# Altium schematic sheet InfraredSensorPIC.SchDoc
size A; SheetNumber: 1; SheetTotal: 1
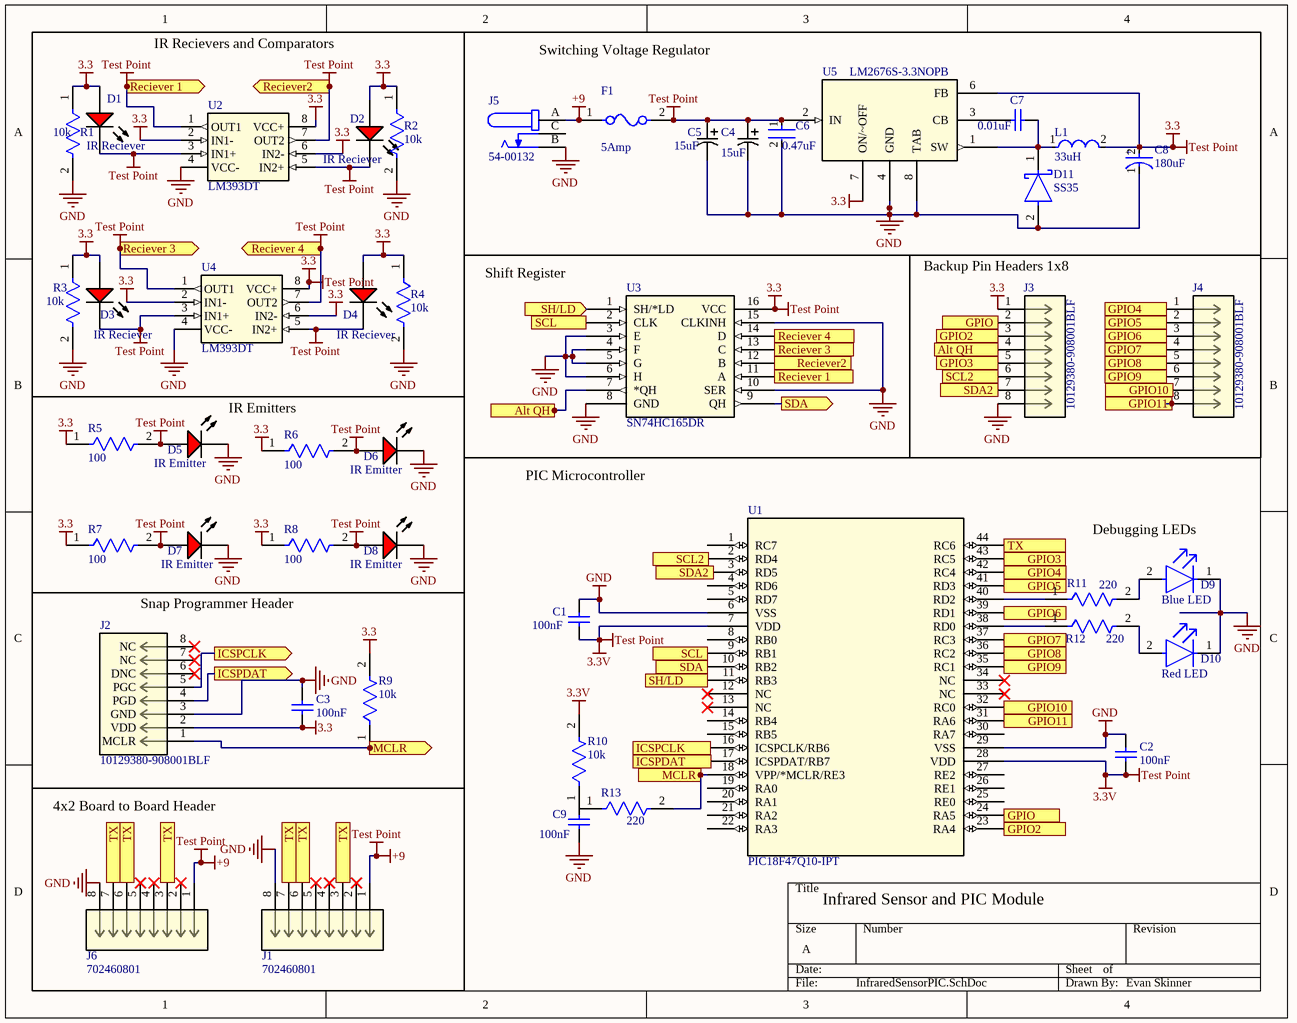
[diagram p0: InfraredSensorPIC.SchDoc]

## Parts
C1  100nF  [CAPC2013X140X50LL20T25]
C2  100nF  [CAPC2013X140X50LL20T25]
C3  100nF  [CAPC2013X140X50LL20T25]
C4  15uF  [TACR_AVX]
C5  15uF  [TACR_AVX]
C6  0.47uF  [FP-CL21-IPC_A]
C7  0.01uF  [CAPC2013X145X50ML20T25]
C8  180uF  [FP-SP-Cap-X-MFG]
C9  100nF  [CAPC2013X140X50LL20T25]
D1  IR Reciever  [AVAG-HLMP-3301-2]
D2  IR Reciever  [AVAG-HLMP-3301-2]
D3  IR Reciever  [AVAG-HLMP-3301-2]
D4  IR Reciever  [AVAG-HLMP-3301-2]
D5  IR Emitter  [AVAG-HLMP-3301-2]
D6  IR Emitter  [AVAG-HLMP-3301-2]
D7  IR Emitter  [AVAG-HLMP-3301-2]
D8  IR Emitter  [AVAG-HLMP-3301-2]
D9  Blue LED  [FP-6_541-5093_01-4-MFG]
D10  Red LED  [FP-6_541-5092_01-4-MFG]
D11  SS35  [FP-403AG-MFG]
F1  5Amp  [FP-0154-MFG]
J1  702460801  [CONN_7024608xx_MOL]
J2  10129380-908001BLF  [CONN_10129380-x08001xLF_AMP]
J3  10129380-908001BLF  [CONN_10129380-x08001xLF_AMP]
J4  10129380-908001BLF  [CONN_10129380-x08001xLF_AMP]
J5  54-00132  [TENSILITY_54-00132]
J6  702460801  [CONN_7024608xx_MOL]
L1  33uH  [FP-LQH32CH_53-MFG]
R1  10k  [FP-CR0805-IPC_A]
R2  10k  [FP-CR0805-IPC_A]
R3  10k  [FP-CR0805-IPC_A]
R4  10k  [FP-CR0805-IPC_A]
R5  100  [FP-CRCW0805-HPe3-IPC_C]
R6  100  [FP-CRCW0805-HPe3-IPC_C]
R7  100  [FP-CRCW0805-HPe3-IPC_C]
R8  100  [FP-CRCW0805-HPe3-IPC_C]
R9  10k  [FP-CR0805-IPC_A]
R10  10k  [FP-CR0805-IPC_A]
R11  220  [FP-CRCW0805-e3-MFG]
R12  220  [FP-CRCW0805-e3-MFG]
R13  220  [FP-CRCW0805-e3-MFG]
U1  PIC18F47Q10-IPT  [TQFP44_PT_MCH]
U2  LM393DT  [SO8_STM]
U3  SN74HC165DR  [D16]
U4  LM393DT  [SO8_STM]
U5  LM2676S-3.3NOPB  [TS7B]

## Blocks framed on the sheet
Switching Voltage Regulator: C4-C8 D11 F1 J5 L1 U5
Snap Programmer Header: C3 J2 R9
4x2 Board to Board Header: J1 J6

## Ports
Alt QH (out, see InfraredSensorPIC[2B]), Alt QH (out, see InfraredSensorPIC[3B]), GPIO2 (see InfraredSensorPIC[3B]), GPIO2 (see InfraredSensorPIC[4D]), GPIO3 (see InfraredSensorPIC[3B]), GPIO3 (see InfraredSensorPIC[4C]), GPIO4 (see InfraredSensorPIC[4B]), GPIO4 (see InfraredSensorPIC[4C]), GPIO5 (see InfraredSensorPIC[4B]), GPIO5 (see InfraredSensorPIC[4C]), GPIO6 (see InfraredSensorPIC[4B]), GPIO6 (see InfraredSensorPIC[4C]), GPIO7 (see InfraredSensorPIC[4B]), GPIO7 (see InfraredSensorPIC[4C]), GPIO8 (see InfraredSensorPIC[4B]), GPIO8 (see InfraredSensorPIC[4C]), GPIO9 (see InfraredSensorPIC[4B]), GPIO9 (see InfraredSensorPIC[4C]), GPIO10 (see InfraredSensorPIC[4B]), GPIO10 (see InfraredSensorPIC[4C]), GPIO11 (see InfraredSensorPIC[4B]), GPIO11 (see InfraredSensorPIC[4C]), GPIO (see InfraredSensorPIC[3B]), GPIO (see InfraredSensorPIC[4D]), ICSPCLK (in, see InfraredSensorPIC[1C]), ICSPCLK (out, see InfraredSensorPIC[2C]), ICSPDAT (in, see InfraredSensorPIC[1C]), ICSPDAT (out, see InfraredSensorPIC[2C]), MCLR (in, see InfraredSensorPIC[2C]), MCLR (out, see InfraredSensorPIC[2D]), Reciever2 (in, see InfraredSensorPIC[1A]), Reciever2 (out, see InfraredSensorPIC[3B]), Reciever 1 (in, see InfraredSensorPIC[1A]), Reciever 1 (out, see InfraredSensorPIC[3B]), Reciever 3 (in, see InfraredSensorPIC[1A]), Reciever 3 (out, see InfraredSensorPIC[3B]), Reciever 4 (in, see InfraredSensorPIC[1A]), Reciever 4 (out, see InfraredSensorPIC[3B]), SCL2 (out, see InfraredSensorPIC[3B]), SCL2 (out, see InfraredSensorPIC[3C]), SCL (in, see InfraredSensorPIC[3C]), SCL (out, see InfraredSensorPIC[2B]), SDA2 (in, see InfraredSensorPIC[3B]), SDA2 (in, see InfraredSensorPIC[3C]), SDA (in, see InfraredSensorPIC[3B]), SDA (out, see InfraredSensorPIC[3C]), SH/LD (in, see InfraredSensorPIC[2C]), SH/LD (out, see InfraredSensorPIC[2B]), TX (in, see InfraredSensorPIC[1D], InfraredSensorPIC[2D], InfraredSensorPIC[4C]), TX (in, see InfraredSensorPIC[1D], InfraredSensorPIC[4C]), TX (out, see InfraredSensorPIC[1D], InfraredSensorPIC[2D])

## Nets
+9: C1.2 C2.2 C3.2 C4.1 C5.1 C6.1 C8.2(A) D1.1(K) D1.2(A) D2.1(K) D2.2(A) D3.1(K) D3.2(A) D4.1(K) D4.2(A) D5.2(A) D6.2(A) D7.2(A) D8.2(A) F1.1 F1.2 J1.1 J2.2(VDD) J3.1 J5.A J6.1 L1.2 R1.1 R2.1 R3.1 R4.1 R5.1 R5.2 R6.1 R6.2 R7.1 R7.2 R8.1 R8.2 R9.2 R10.2 U1.7(VDD) U1.28(VDD) U2.1(OUT1) U2.2(IN1-) U2.3(IN1+) U2.5(IN2+) U2.6(IN2-) U2.7(OUT2) U2.8(VCC+) U3.11(A) U3.12(B) U3.13(C) U3.14(D) U3.16(VCC) U4.1(OUT1) U4.2(IN1-) U4.3(IN1+) U4.5(IN2+) U4.6(IN2-) U4.7(OUT2) U4.8(VCC+) U5.2(IN) U5.6(FB) U5.7(ON/~OFF) ; port Reciever 1, port Reciever2, port Reciever 3, port Reciever 4  [also labelled 3.3, 3.3V, Test Point]
GND: C1.1 C2.1 C3.1 C4.2 C5.2 C6.2 C8.1(C) C9.2 D5.1(K) D6.1(K) D7.1(K) D8.1(K) D9.1(C) D10.1(C) D11.2(A) J1.8 J2.3(GND) J3.8 J5.B J6.8 R1.2 R2.2 R3.2 R4.2 U1.6(VSS) U1.29(VSS) U2.4(VCC-) U3.3(E) U3.4(F) U3.5(G) U3.6(H) U3.8(GND) U3.10(SER) U3.15(CLKINH) U4.4(VCC-) U5.4(GND) U5.8(TAB)
Alt QH: J3.4 U3.7(*QH) ; port Alt QH
GPIO: J3.2 U1.24(RA5) ; port GPIO
GPIO2: J3.3 U1.23(RA4) ; port GPIO2
GPIO3: J3.5 U1.43(RC5) ; port GPIO3
GPIO4: J4.1 U1.42(RC4) ; port GPIO4
GPIO5: J4.2 U1.41(RD3) ; port GPIO5
GPIO6: J4.3 U1.39(RD1) ; port GPIO6
GPIO7: J4.4 U1.37(RC3) ; port GPIO7
GPIO8: J4.5 U1.36(RC2) ; port GPIO8
GPIO9: J4.6 U1.35(RC1) ; port GPIO9
GPIO10: U1.32(RC0) ; port GPIO10
GPIO11: J4.8 U1.31(RA6) ; port GPIO11
ICSPCLK: J2.5(PGC) ; port ICSPCLK
ICSPDAT: J2.4(PGD) ; port ICSPDAT
MCLR: J2.1(MCLR) R9.1 R13.2 U1.18(VPP/*MCLR/RE3) ; port MCLR
SCL: U1.9(RB1) U3.2(CLK) ; port SCL
SCL2: J3.6 ; port SCL2
SDA: U1.10(RB2) U3.9(QH) ; port SDA
SDA2: J3.7 ; port SDA2
SH/LD: U1.11(RB3) U3.1(SH/*LD) ; port SH/LD
TX: J1.3 J1.6 J1.7 J6.3 J6.6 J6.7 U1.44(RC6) ; port TX
NetC7_1: C7.1 U5.3(CB)
NetC7_2: C7.2 D11.1(C) L1.1 U5.1(SW)
NetD9_2: D9.2(A) R11.2
NetD10_2: D10.2(A) R12.2
NetR10_1: R10.1 R13.1
NetR11_1: R11.1 U1.40(RD2)
NetR12_1: R12.1 U1.38(RD0)

Not connected (* = marked no-connect by the designer): C9 1; J1 2* 4* 5*; J2 6(DNC)* 7(NC)* 8(NC)*; J4 7; J5 C; J6 2* 4* 5*; U1 1(RC7) 2(RD4) 3(RD5) 4(RD6) 5(RD7) 8(RB0) 12(NC)* 13(NC)* 14(RB4) 15(RB5) 16(ICSPCLK/RB6) 17(ICSPDAT/RB7) 19(RA0) 20(RA1) 21(RA2) 22(RA3) 25(RE0) 26(RE1) 27(RE2) 30(RA7) 33(NC)* 34(NC)*

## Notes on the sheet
- IR Recievers and Comparators
- (near U3) Shift Register
- (near J3) Backup Pin Headers 1x8
- IR Emitters
- PIC Microcontroller
- Debugging LEDs
- Infrared Sensor and PIC Module
- Evan Skinner

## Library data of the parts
C1-C3 C9 = CMP-2007-04740-1: Part Number: 08051C104M4Z2A; Manufacturer: AVX Interconnect / Elco
C4 C5 = TACR156K010XTA: No Description Available; Mfr_Name: KYOCERA AVX
C6 = CMP-13271-002452-1: CL21 Series 0805 470nF 50V ±10% Tolerance X7R Multilayer Ceramic Chip Capacitor
C7 = CMP-2007-01059-1: Manufacturer: Kemet; Part Number: C0805W103KCRACTU
C8 = CMP-05428-000369-1: Molded Aluminum Polymer Capacitor 180uF 20% 2V life 2000Hours SMD 2917; ESR (Equivalent Series Resistance): 9mR; Life (Hours): 1000Hour; Ripple Current: 3A; Dielectric Material: Aluminium; Dissipation Factor: 0.06%; Leakage Current: 36uA
D1-D8 = CMP-2000-06411-1: T-1 3/4 (5 mm) Diffused LED Lamp, 1.9 V, -40 to 100 degC, 2-Pin THD, RoHS, Bulk; Manufacturer: Avago; Forward Current: 25mA; Forward Voltage: 2.4V; Peak Wavelength: 635nm; Shape Type: Circular; High Brightness: No; Main Category: StandardLED; Test Current (It): 10mA; Dominant Wave Length: 626nm; Number of  Elements: 1; Reverse Voltage: 5V; Chip Material: GaP; Product Height (mm): 9.19mm; Lens Type: ColoredDiffused; Viewing Angle: 60deg; Type: Uni-Color; Emitting Color: Red; Luminous Intensity: 5.4mcd; Power Dissipation: 85W; DELETED: Compliant; Product Depth (mm): 6.1mm
D9 = CMP-00030-21709198-1: VLMB1310-GS08 LED Uni-Color Blue 468nm 2-Pin Chip 0603(1608Metric) T/R; Forward Voltage: 3.8V; Forward Current: 20mA; Wavelength: 475nm; Viewing Angle: 130°; Luminous Intensity: 180mcd; Lens Style: Clear, Rectangular; Number of LEDs: 1; Power Rating: 75mW; Dominant Wavelength: 470nm
D10 = CMP-02520-000012-1: LED RED 0603 SMD; Manufacturer: Vishay; Manufacturer Part Number: VLMS1300-GS08; Forward Voltage: 2V; Reverse Voltage: 5V; Power Dissipation: 75mW; Description: Red 631nm LED Indication - Discrete 2V 0603 (1608 Metric); Forward Current: 20mA; Luminous Intensity: 54mcd; Led Orientation: Top View; Peak Emmision Wavelength: 639nm; Viewing Angle: 130°; Wavelength: 631nm
D11 = CMP-00278-84331626-1: SS35 Rectifier Diode, Schottky, 1 Phase, 1 Element, 3A, 50V V(RRM), Silicon, DO-214AB; Manufacturer Lifecycle Status: ACTIVE, NOT REC; Max Forward Surge Current (Ifsm): 100A; Forward Voltage: 750mV; Max Reverse Leakage Current: 500µA; Element Configuration: Single; Polarity: Standard
F1 = CMP-08605-000036-1: FUSE BOARD MNT 250MA 125VAC/VDC; Manufacturer Part Number: 0154.250DR; Manufacturer: Littelfuse; Fuse Blow Speed: Fast; Description: 250mA 125V AC 125V DC Fuse Board Mount (Cartridge Style Excluded) Holder, Surface Mount 2-SMD, Square End Block with Holder; Fuse I2T: 0.0113A2Sec; Voltage Rating: 125V; Fuse Current: 0.25A
J1 J6 = 702460801: No Description Available; Mfr_Name: Molex Connector Corporation
J2-J4 = 10129380-908001BLF: No Description Available; Mfr_Name: Amphenol ICC
J5 = 54-00132: Connector, dc jack 5.5x2.5 mm, PCB mount, 90 degrees, silver plated, board lock; MF: Tensility International Corp
L1 = CMP-06042-002142-1: Wire Wound Ferrite Inductor for Power Lines 33μH ±10% 1.43Ω 200mA 1210; Test Frequency: 1MHz; Shielding: Unshielded; DC Resistance (DCR): 1.1R; Self Resonant Frequency: 17MHz
R1-R4 R9 R10 = CMP-07231-003204-1: Thick Film Chip Resistors 0805 10kΩ 0.125W 1% 100ppm/°C; Max Power Dissipation: 125mW; Voltage Rating: 150V; Voltage Rating (DC): 100V; Resistance: 10kR
R5-R8 = CMP-02407-002130-1: RES Thick Film, 100Ω, 5%, 0.5W, 200ppm/°C, 0805; Voltage Rating: 150V; Resistance: 100R; Power Rating: 330mW; Max Power Dissipation: 333mW
R11-R13 = CMP-2001-03682-2: RES Thick Film, 220Ω, 1%, 0.125W, 100ppm/°C, 0805; Max Power Dissipation: 125mW; Voltage Rating: 150V; Resistance: 220R
U1 = PIC18F47Q10-IPT: No Description Available; Mfr_Name: Microchip
U2 U4 = LM393DT: No Description Available; Mfr_Name: STMicroelectronics
U3 = SN74HC165DR: No Description Available; Mfr_Name: Texas Instruments
U5 = LM2676S-3.3NOPB: No Description Available; Mfr_Name: Texas Instruments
